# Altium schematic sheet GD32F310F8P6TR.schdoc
size 127 x 101 mm
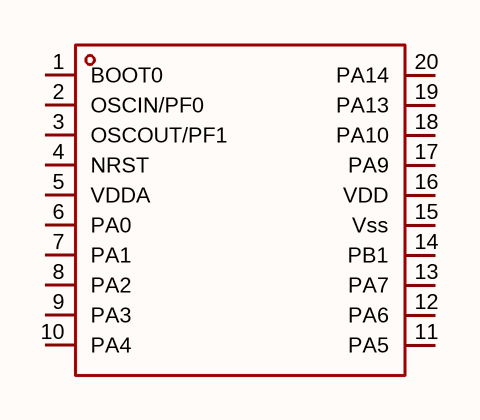
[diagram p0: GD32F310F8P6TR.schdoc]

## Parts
U?  gd32f310f8p6tr  [TSSOP-20_L6.5-W4.4-P0.65-LS6.4-BL]  (value not drawn)

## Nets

Not connected (* = marked no-connect by the designer): U? 1(BOOT0) 2(OSCIN/PF0) 3(OSCOUT/PF1) 4(NRST) 5(VDDA) 6(PA0) 7(PA1) 8(PA2) 9(PA3) 10(PA4) 11(PA5) 12(PA6) 13(PA7) 14(PB1) 15(Vss) 16(VDD) 17(PA9) 18(PA10) 19(PA13) 20(PA14)

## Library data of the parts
U? = gd32f310f8p6tr: CPU内核:ARM Cortex-M4;CPU最大主频:72MHz;; Manufacturer: GigaDevice(兆易创新); AddInBom: yes; ModelId: c491f68934b34c649df5890a1d97cd0f; ModelName: TSSOP-20_L6.5-W4.4-H1.0-LS6.4-P0.65; ModelTransform: 251.969,255.906,0,90,0,0,0.0005,0,0; CPU Maximum Speed: 72MHz; Program Storage Size: 64KB; Program Memory Type: FLASH; EEPROM: 128KB; Number of I/O: 15; ADC (Bit): 12bit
